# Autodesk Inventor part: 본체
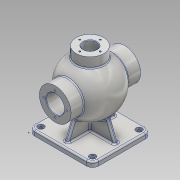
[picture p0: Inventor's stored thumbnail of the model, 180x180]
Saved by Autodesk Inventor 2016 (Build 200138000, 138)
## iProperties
Created: 2017-01
Part Number: 본체
Material: 알루미늄 6061
Document SubType Name: Modeling
Designer: Administrator
Density: 2.7 g/cm^3
Appearance: 알루미늄 - 평지
Mass: 1504.05 g
Surface Area: 1153.86 cm^2
Volume: 557.055 cm^3
Author: Administrator
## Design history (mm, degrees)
sketch "스케치1"
  geometry: L1 (0, 0)-(125, 0); L2 (125, 0)-(125, 115); L3 (125, 115)-(0, 115); L4 (0, 115)-(0, 0)
  constraints: 8 end point, 2 parallel, 1 horizontal, 1 perpendicular
  dimensions: "d0" = 125 distance between parallel lines of L2 L4; "d1" = 115 distance between parallel lines of L1 L3
extrude "돌출1" new body sketch "스케치1" distance "d2" = 10; taper "d3" = 0 deg
fillet "모깎기1" dims "d4" = 12
sketch "스케치2"
  geometry: A1 r 12 centre (12, 103) between (12, 115) and (0, 103) reference; A2 r 12 centre (113, 103) between (125, 103) and (113, 115) reference; A3 r 12 centre (113, 12) between (113, 0) and (125, 12) reference; A4 r 12 centre (12, 12) between (0, 12) and (12, 0) reference; 5 further points
  constraints: 4 coincident
hole "구멍1" sketch "스케치2" at (12, 103), (113, 103), (113, 12), (12, 12) diameter "d5" = 8; stored, may be unused: countersink angle "d9" = 90 deg, drill point angle "d11" = 118 deg; dims "d6" = 6, "d7" = 12, "d8" = 3, "d10" = 8
node "작업 평면2"
sketch "스케치5"
  geometry: L1 (0, 91)-(0, 0) reference; L2 (0, 45.5)-(-120.31, 45.5); L3 (-85, -22.5)-(-85, 113.5); L4 (-85, -22.5)-(-116, -22.5); L5 (-116, -22.5)-(-116, 2.512); L6 (-116, 88.488)-(-116, 113.5); L7 (-116, 113.5)-(-85, 113.5); A1 r 53 centre (-85, 45.5) between (-116, 88.488) and (-116, 2.512); 1 further point
  constraints: 12 end point, 2 horizontal, 2 midpoint, 2 perpendicular, 2 point on circle, 2 vertical, 1 centre point, 1 point on line
  dimensions: "d31" = 106 diameter of A1; "d32" = 85 distance between parallel lines of L1 L3; "d33" = 31 distance between parallel lines of L3 L5; "d34" = 31 distance between parallel lines of L3 L6; "d35" = 136 distance between parallel lines of L7 L4; "d36" = 68 distance between parallel lines of L4 L2
revolve "회전2" sketch "스케치5" stored, may be unused: angle "d37" = 90 deg
sketch "스케치6"
  geometry: L1 (-54, -22.5)-(-116, -22.5) reference; L2 (-85, -22.5)-(-85, 113.5); L3 (-54, 113.5)-(-116, 113.5) reference; L4 (-85, -22.5)-(-102.5, -22.5); L5 (-102.5, -22.5)-(-102.5, 6.222); L6 (-85, 113.5)-(-102.5, 113.5); L7 (-102.5, 95.75)-(-103.5, 95.75); L8 (-103.5, 95.75)-(-103.5, 97.5); L9 (-103.5, 97.5)-(-102.5, 97.5); L10 (-102.5, 84.778)-(-102.5, 95.75); L11 (-102.5, 97.5)-(-102.5, 113.5); A1 r 43 centre (-85, 45.5) between (-102.5, 84.778) and (-102.5, 6.222); 1 further point
  constraints: 18 end point, 3 midpoint, 3 perpendicular, 3 point on line, 2 parallel, 2 point on circle, 1 centre point, 1 vertical
  dimensions: "d38" = 86 diameter of A1; "d39" = 17.5 distance between parallel lines of L2 L5; "d40" = 17.5 distance between parallel lines of L2 L10; "d41" = 16 distance between parallel lines of L3 L9; "d42" = 1.75 distance between parallel lines of L7 L9; "d43" = 18.5 distance between parallel lines of L2 L8
revolve "회전3" sketch "스케치6" stored, may be unused: angle "d44" = 90 deg
sketch "스케치7"
  geometry: C1 r 17.5 at (0, 0) reference; A1 r 22.5 centre (0, 0) between (0, 22.5) and (22.5, 0); 3 further points
  constraints: 4 point on circle, 1 centre point, 1 coincident
  dimensions: "d45" = 45 diameter of A1
hole "구멍2" sketch "스케치7" at (0, 22.5), (22.5, 0), (0, -22.5), (-22.5, 0) diameter "d46" = 3.242; stored, may be unused: countersink angle "d50" = 90 deg, drill point angle "d52" = 118 deg; dims "d47" = 12, "d48" = 12, "d49" = 3, "d51" = 15
sketch "스케치8"
  geometry: C1 r 17.5 at (0, 0) reference; A1 r 24 centre (0, 0) between (-24, 0) and (0, -24); 3 further points
  constraints: 4 point on circle, 1 centre point, 1 coincident
  dimensions: "d53" = 48 diameter of A1
hole "구멍3" sketch "스케치8" at (-24, 0), (0, -24), (24, 0), (0, 24) diameter "d54" = 3.242; stored, may be unused: countersink angle "d58" = 90 deg, drill point angle "d60" = 118 deg; dims "d55" = 16, "d56" = 12, "d57" = 3, "d59" = 19
node "작업 평면3"
sketch "스케치9"
  geometry: L1 (-31.5, -10.5)-(-93.5, -10.5) reference; L2 (-62.5, -10.5)-(-62.5, 125.5); L3 (-31.5, 125.5)-(-93.5, 125.5) reference; L4 (0, 103)-(0, 12) reference; L5 (0, 57.5)-(-125, 57.5); L6 (-125, 12)-(-125, 103) reference; C1 r 27 at (-62.5, 57.5); 1 further point
  constraints: 4 end point, 4 midpoint, 1 centre point
  dimensions: "d62" = 54 diameter of C1; "d63" = 0 distance from line of C1.centre L2; "d64" = 0 distance from line of L5 C1.centre
extrude "돌출2" join sketch "스케치9" stored distance "d65" = 10; taper "d66" = 0 deg
sketch "스케치10"
  geometry: C1 r 27 at (0, 0) reference; C2 r 13 at (0, 0); 1 further point
  constraints: 1 centre point, 1 coincident
  dimensions: "d67" = 26 diameter of C2
extrude "돌출3" cut sketch "스케치10" distance "d68" = 60.25; taper "d69" = 0 deg
sketch "스케치11"
  geometry: C1 r 13 at (0, 0) reference; A1 r 20 centre (0, 0) between (0, 20) and (20, 0); 3 further points
  constraints: 4 point on circle, 1 centre point, 1 coincident
  dimensions: "d70" = 40 diameter of A1
hole "구멍4" sketch "스케치11" at (0, 20), (20, 0), (0, -20), (-20, 0) diameter "d71" = 3.242; stored, may be unused: countersink angle "d75" = 90 deg, drill point angle "d77" = 118 deg; dims "d72" = 9, "d73" = 12, "d74" = 3, "d76" = 11
sketch "스케치12"
  geometry: L1 (-10, 91)-(-10, 0) reference; L2 (-85.332, 45.09)-(-10, 45.5); L3 (-44.107, 11.78)-(-10, -2); L4 (-44.613, 79.016)-(-10, 93); L5 (-10, -12)-(-10, 0) reference; L6 (-10, 91)-(-10, 103) reference; L7 (-10, -12)-(-10, 103); L8 (-10, 103)-(0, 103) reference; L9 (0, -12)-(-10, -12) reference; L10 (-10, -2)-(-10, 93); A1 r 53 centre (-85.332, 45.09) between (-44.107, 11.78) and (-44.613, 79.016); A2 r 53 centre (-85.332, 45.09) between (-44.107, 11.78) and (-44.613, 79.016)
  constraints: 10 end point, 4 point on circle, 2 centre point, 2 coincident, 2 point on line, 1 collinear, 1 midpoint, 1 vertical
  dimensions: "d79" = 10 distance from line of L8 L4.end; "d80" = 10 distance from line of L9 L3.end; "d81" = 112 deg angle of L5 L3; "d82" = 112 deg angle of L4 L6; "d84" = 106 diameter of A2
extrude "돌출4" join sketch "스케치12" stored distance "d85" = 8; taper "d86" = 0 deg
node "작업 평면4"
sketch "스케치13" dims "d88" = 106
  geometry: L1 (13.121, 47.426)-(-2, 10); L2 (0, 10)-(0, 0) reference; L3 (95, 10)-(107, 10) reference; L4 (0, 10)-(107, 10); L5 (-12, 0)-(-12, 10) reference; L6 (-12, 10)-(0, 10) reference; C1 r 17.5 at (50.5, 85) reference; 1 further point
  constraints: 4 end point, 1 coincident, 1 horizontal, 1 point on line, 3 other
  dimensions: "d89" = 10 distance from line of L5 L1.end; "d90" = 112 deg angle of L6 L1
feature "리브1" sketch "스케치13" dims "d91" = 1, "d92" = 8, "d93" = 0, "d94" = 0, "d95" = 1, "d96" = 1
sketch "스케치14" dims "d97" = 106
  geometry: L1 (103, 10)-(87.879, 47.426); L2 (46.5, 10)-(54.5, 10) reference; L3 (101, 10)-(113, 10) reference; L4 (54.5, 10)-(113, 10); L5 (113, 10)-(113, 0) reference; C1 r 17.5 at (50.5, 85) reference; 2 further points
  constraints: 4 end point, 1 coincident, 1 collinear, 1 point on line, 3 other
  dimensions: "d98" = 10 distance from line of L5 L1.start; "d99" = 112 deg angle of L1 L3
feature "리브2" sketch "스케치14" dims "d100" = 1, "d101" = 8, "d102" = 0, "d103" = 0, "d104" = 1, "d105" = 1
fillet "모깎기2" dims "d106" = 3
fillet "모깎기3" dims "d107" = 3
chamfer "모따기1" distance "d108" = 1; stored, may be unused: second distance "d109" = 2, angle "d110" = 45 deg
sketch "스케치15"
  geometry: 1 further point
node "작업 평면5"
sketch "스케치16"
  geometry: L1 (136.006, 59.067)-(136.006, 31.933); L2 (136.006, 31.933)-(143.994, 31.933); L3 (143.994, 31.933)-(143.994, 59.067); L4 (143.994, 59.067)-(136.006, 59.067); L5 (150, 18.5)-(150, 72.5) reference; L6 (116, 113.5)-(54, 113.5) reference; 3 further points
  constraints: 2 midpoint, 2 other
  dimensions: "d112" = 10 distance from line of L5 point (140, 31.933); "d113" = 68 distance from line of L6 point (143.994, 45.5)
feature "엠보싱1" sketch "스케치16" dims "d0" = 125, "d1" = 115, "d7" = 12, "d114" = 0.5, "d115" = 0
node "솔리드1"
other parameters: "d30" = -62.5, "d87" = -57.5, "d111" = 16.75
